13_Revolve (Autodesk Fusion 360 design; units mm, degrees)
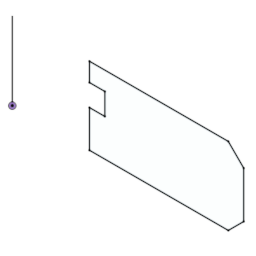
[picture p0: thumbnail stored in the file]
part number: 2026-07-16-12-29-54-527
sketch "Sketch1" plane through (0, 0, 0) normal (0, 1, 0) x axis (1, 0, 0)
  line L1 (0, -25) -> (0, 0)
  line L2 (70, 0) -> (25, 0)
  line L3 (75, -5) -> (70, 0)
  line L4 (75, -20) -> (75, -5)
  line L5 (70, -25) -> (75, -20)
  line L6 (25, -25) -> (70, -25)
  line L7 (25, -19) -> (25, -25)
  line L8 (30, -19) -> (25, -19)
  line L9 (30, -12) -> (30, -19)
  line L10 (25, -12) -> (30, -12)
  line L11 (25, 0) -> (25, -12)
  point P1 (0, 0)
  point P2 (0, 0)
  point P3 (0, -25)
  point P4 (25, 0)
  point P13 (25, -12)
  point P12 (30, -12)
  point P11 (30, -19)
  point P7 (75, -20)
  point P8 (70, -25)
  coincident P1 P2
  vertical L1
  perpendicular L1 L2
  perpendicular L2 L4
  perpendicular L4 L6
  perpendicular L6 L7
  perpendicular L7 L8
  perpendicular L8 L9
  perpendicular L9 L10
  perpendicular L2 L11
  coincident P1 L2
  collinear L7 L11
  coincident P3 L6
  equal L3 L5
  dimension "d1" distance P2 P3 = 25
  dimension "d2" distance P4 P13 = 12
  dimension "d3" distance P12 P13 = 5
  dimension "d4" distance P11 P12 = 7
  dimension "d5" angle L2 L3 = 45
  dimension "d6" angle L5 L6 = 45 (= "d5")
  dimension "d7" distance P7 P8 = 5
  dimension "d9" distance L1 L11 = 25
  dimension "d10" distance L1 L4 = 75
